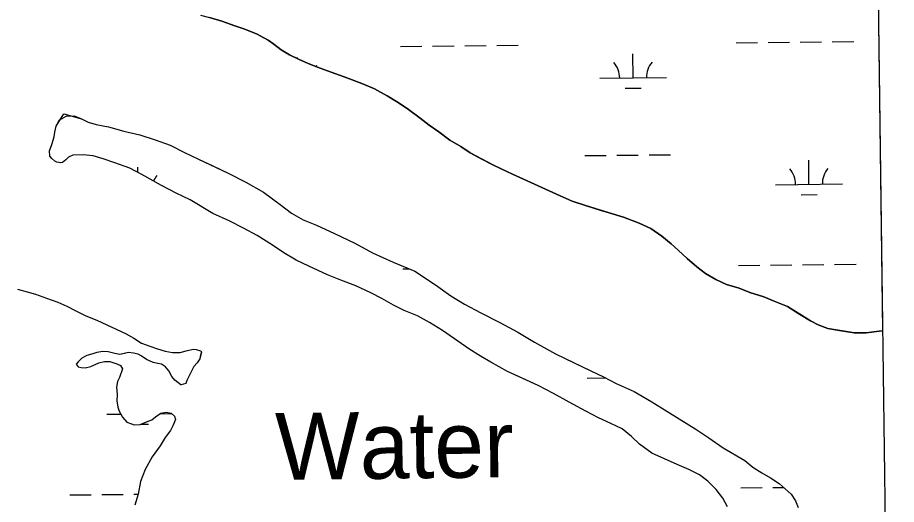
# Model space of a CAD drawing. Extents: x 3734862 to 3772949, y 391520 to 417239.
# Drawn here: x 3769529 to 3770844, y 398541 to 399269 of the extents above; entities that cross this region are included whole.
import ezdxf

# ---------------------------------------------------------------- set-up
doc = ezdxf.new("R2010")
doc.units = 0
for name, color, linetype in [('V-GRID-FRAM', 7, 'Continuous'), ('V-RIVR-IDEN', 7, 'Continuous'), ('V-TOPO-SHOR', 7, 'Continuous'), ('V-WETL-SWMP', 7, 'Continuous')]:
    doc.layers.add(name, color=color, linetype=linetype)

msp = doc.modelspace()

# ---------------------------------------------------------------- linework, layer by layer
at = {"layer": 'V-GRID-FRAM'}
msp.add_lwpolyline([(3738832.3, 415033.8), (3770599.2, 415447.4), (3770843.8, 397266.6), (3739061.1, 396852.8), (3738832.3, 415033.8)], dxfattribs=at)
at = {"layer": 'V-TOPO-SHOR'}
for points in [[(3769802.6, 399272.3), (3769816, 399268.8), (3769834.8, 399263.3), (3769854.3, 399256.6), (3769867.4, 399252), (3769886.5, 399244.5), (3769904.1, 399235.2), (3769912.5, 399229), (3769923.6, 399220.5), (3769935.9, 399213.1), (3769949.3, 399206.5), (3769963.8, 399200.3), (3769981.8, 399193.3), (3769998.3, 399187.4), (3770017.5, 399180.4), (3770029.7, 399175.7), (3770046.6, 399169), (3770063.1, 399162.4), (3770081.8, 399151.9), (3770096, 399143.4), (3770112, 399132.9), (3770131.2, 399118.6), (3770144.9, 399107.7), (3770159.1, 399098.1), (3770175.9, 399085.7), (3770192.4, 399076), (3770206.1, 399066.7), (3770223.7, 399057.3), (3770239.8, 399048.8), (3770252.4, 399042.6), (3770269.7, 399034.8), (3770340.9, 399002.1), (3770358.9, 398994.3), (3770378.5, 398987.6), (3770400.7, 398981), (3770414.1, 398977), (3770435.6, 398970.4), (3770459, 398961.4), (3770476.6, 398953.2), (3770493, 398942), (3770506.8, 398930.4), (3770517.1, 398921.1), (3770530.8, 398908.3), (3770545, 398896), (3770558, 398886.3), (3770573.7, 398877), (3770589.8, 398869.9), (3770608.5, 398864.1), (3770624.6, 398857.8), (3770645.3, 398851.2), (3770661, 398844.9), (3770680.6, 398836.7), (3770698.9, 398825.5), (3770715.4, 398815.4), (3770726.9, 398809.2), (3770741.4, 398803.7), (3770758.7, 398800.9), (3770780.6, 398797.3), (3770798.6, 398797.2), (3770817.8, 398799.8), (3770823.2, 398800.6)], [(3769577.4, 399061.8), (3769576.7, 399069.6), (3769580.2, 399079), (3769583.8, 399090.3), (3769584.6, 399097.3), (3769586.7, 399106.3), (3769598.5, 399124.8)], [(3769598.5, 399124.8), (3769624.6, 399117.3), (3769634.7, 399112.6), (3769646.4, 399109), (3769665.1, 399105.4), (3769688.1, 399099), (3769711.9, 399093.4), (3769734.9, 399086.2), (3769757.5, 399077.9), (3769778.9, 399067.2), (3769799.5, 399057.3), (3769821.3, 399047), (3769843.9, 399036.3), (3769870.4, 399022.9), (3769896.8, 399007.9), (3769922.1, 398989.4), (3769938.8, 398976.4), (3769956.3, 398966.5), (3769976.2, 398958.6), (3770003.4, 398945.9), (3770033.4, 398931.3), (3770059.9, 398917.1), (3770091, 398903.2), (3770123.3, 398889.4), (3770154.5, 398869.3), (3770177, 398852.7), (3770197.6, 398840.1), (3770222.1, 398827.1), (3770250.5, 398812.8), (3770277.4, 398798.6), (3770302.3, 398783.2), (3770333.8, 398765.9), (3770362.6, 398752), (3770386.8, 398740.6), (3770405.4, 398731.8), (3770424.5, 398721.6), (3770451.4, 398709.7), (3770477.8, 398694.3), (3770500.4, 398680.1), (3770522.6, 398666.3), (3770543.6, 398653.3), (3770563.4, 398640.3), (3770584.8, 398625.3), (3770617.1, 398606.4), (3770629.1, 398596.5), (3770642.3, 398588.3), (3770655.6, 398580.8), (3770668.4, 398572.1), (3770686.3, 398556), (3770692.8, 398546.2), (3770696.7, 398536)], [(3769642.2, 399062.2), (3769627.4, 399063.8), (3769611.8, 399063.2), (3769605.1, 399060.1), (3769601.2, 399056.2), (3769596.5, 399051.9), (3769593.7, 399051.6), (3769587.9, 399052.8), (3769584.8, 399054.3), (3769580.5, 399057.9), (3769577.4, 399061.8)], [(3770591.3, 398537.4), (3770584.3, 398550.4), (3770573.9, 398563.3), (3770561.8, 398575.5), (3770549, 398585.3), (3770533, 398592.8), (3770515.9, 398600.4), (3770496.8, 398609.1), (3770477.8, 398617.4), (3770459.5, 398630.8), (3770447.4, 398642.2), (3770433.5, 398653.6), (3770416.7, 398661.9), (3770398, 398670.2), (3770379.4, 398680.5), (3770354.1, 398693.5), (3770330.7, 398706.9), (3770307.8, 398718.8), (3770284, 398729.5), (3770262.2, 398739.4), (3770236.9, 398753.6), (3770221.7, 398762.7), (3770204.2, 398773.3), (3770182.8, 398788.3), (3770164.6, 398800.9), (3770145.1, 398812.7), (3770127.2, 398822.6), (3770107.4, 398830.9), (3770091.4, 398838.8), (3770073.9, 398848.7), (3770057.6, 398857.4), (3770035, 398867.7), (3770012.8, 398876), (3769992.5, 398884.3), (3769964.9, 398897), (3769945.8, 398906.1), (3769927.5, 398917.1), (3769910.4, 398928.6), (3769887.5, 398942.8), (3769867.2, 398953.8), (3769845.4, 398964.9), (3769821.3, 398976), (3769787.4, 398996.1), (3769766.4, 399006), (3769744.2, 399017.8), (3769715.1, 399034), (3769696.8, 399043.5), (3769674.6, 399051.8), (3769657, 399057.8), (3769642.2, 399062.2)], [(3769528.9, 398862.6), (3769543.3, 398858.6), (3769555.8, 398855), (3769572.2, 398849.4), (3769589.3, 398843.1), (3769603, 398837.5), (3769615, 398830.8), (3769631.4, 398822.9), (3769647.7, 398816.2), (3769691.3, 398796), (3769703, 398789.3), (3769714.7, 398781.8), (3769726.7, 398777.4), (3769738.4, 398773.4), (3769749.7, 398769.9), (3769760.7, 398767.8), (3769772.4, 398767.8), (3769781.4, 398770.4), (3769791.5, 398773.1), (3769796.2, 398772.7), (3769802.8, 398770.3), (3769804, 398769.1), (3769802.4, 398762.1), (3769801.6, 398758.6), (3769797.7, 398752.4), (3769792.9, 398746.9), (3769788.2, 398738), (3769782.3, 398725.9), (3769780.7, 398721.6), (3769774, 398719.7), (3769773.2, 398719.7), (3769764.3, 398726.4), (3769759.7, 398732.3), (3769755.4, 398740.5), (3769750.4, 398746.4), (3769744.5, 398750.4), (3769738.7, 398751.6), (3769731.7, 398753.2), (3769721.9, 398757.5), (3769714.2, 398763.1), (3769709.5, 398765.4), (3769702.5, 398767), (3769695.1, 398767.9), (3769689.2, 398766.7), (3769681.8, 398765.2), (3769674.4, 398766.4), (3769670.5, 398767.6), (3769664.6, 398769.2), (3769656.4, 398769.7), (3769647.8, 398767.8), (3769641.6, 398765.8), (3769632.6, 398763.6)], [(3769632.6, 398763.6), (3769625.1, 398759.3), (3769619.6, 398753.9), (3769616.9, 398750.4), (3769617.6, 398748.8), (3769618.4, 398748.4), (3769619.6, 398746.8), (3769624.3, 398745.6), (3769630.1, 398745.2), (3769638.7, 398747.1), (3769650.8, 398752.5), (3769659.1, 398754.4), (3769666.9, 398754.4), (3769677.8, 398750.8), (3769683.2, 398748.4), (3769685.9, 398743.7), (3769681.6, 398730.8), (3769678.4, 398724.6), (3769677.2, 398716.4), (3769677.9, 398705.1), (3769677.8, 398695.7), (3769679.3, 398686.4), (3769681.2, 398680.5), (3769685.9, 398671.5), (3769692.5, 398664), (3769703.4, 398660), (3769712.4, 398660.4), (3769722.1, 398664.2), (3769730, 398667.3), (3769735.5, 398671.9), (3769743.3, 398677.4), (3769751.5, 398678.9), (3769758.9, 398677.3), (3769763.6, 398672.6), (3769765.1, 398667.9)], [(3769765.1, 398667.9), (3769761.5, 398658.1), (3769757.6, 398651.5), (3769749.7, 398641), (3769742.2, 398628.2), (3769730.4, 398612.2), (3769719.7, 398592.8), (3769713, 398574.9), (3769709.4, 398556.1), (3769704.6, 398539.8)]]:
    msp.add_lwpolyline(points, dxfattribs=at)
at = {"layer": 'V-WETL-SWMP'}
for p, q in [((3770797.7, 400695.1), (3770823.2, 398800.6)), ((3769834.8, 399263.3), (3769816, 399268.8)), ((3769854.3, 399256.6), (3769834.8, 399263.3)), ((3769867.4, 399252), (3769854.3, 399256.6)), ((3769886.5, 399244.5), (3769867.4, 399252)), ((3769904.1, 399235.2), (3769886.5, 399244.5)), ((3769912.5, 399229), (3769904.1, 399235.2)), ((3769923.6, 399220.5), (3769912.5, 399229)), ((3770603.9, 399230.9), (3770635.9, 399231.3)), ((3770651.9, 399231.4), (3770683.9, 399231.8)), ((3770699.9, 399232), (3770731.9, 399232.3)), ((3770747.9, 399232.5), (3770779.9, 399232.8)), ((3769935.9, 399213.1), (3769923.6, 399220.5)), ((3770102.1, 399225.6), (3770134, 399226)), ((3770150, 399226.1), (3770182, 399226.5)), ((3770198, 399226.7), (3770230, 399227)), ((3770246, 399227.2), (3770278, 399227.5)), ((3769949.3, 399206.5), (3769935.9, 399213.1)), ((3769947.6, 399207.3), (3769947.6, 399209.3)), ((3769963.8, 399200.3), (3769949.3, 399206.5)), ((3770449.9, 399178.6), (3770449.5, 399214.6)), ((3769981.8, 399193.3), (3769963.8, 399200.3)), ((3769998.3, 399187.4), (3769981.8, 399193.3)), ((3770017.5, 399180.4), (3769998.3, 399187.4)), ((3770029.7, 399175.7), (3770017.5, 399180.4)), ((3770399.9, 399178), (3770499.9, 399179.1)), ((3770046.6, 399169), (3770029.7, 399175.7)), ((3770063.1, 399162.4), (3770046.6, 399169)), ((3770438, 399163), (3770462, 399163.3)), ((3770081.8, 399151.9), (3770063.1, 399162.4)), ((3770096, 399143.4), (3770081.8, 399151.9)), ((3770112, 399132.9), (3770096, 399143.4)), ((3770131.2, 399118.6), (3770112, 399132.9)), ((3770144.9, 399107.7), (3770131.2, 399118.6)), ((3770159.1, 399098.1), (3770144.9, 399107.7)), ((3770175.9, 399085.7), (3770159.1, 399098.1)), ((3770192.4, 399076), (3770175.9, 399085.7)), ((3770206.1, 399066.7), (3770192.4, 399076)), ((3770239.8, 399048.8), (3770206.1, 399066.7)), ((3770377.7, 399062.4), (3770409.7, 399062.7)), ((3770425.7, 399062.9), (3770457.7, 399063.2)), ((3770473.7, 399063.4), (3770505.7, 399063.7)), ((3769709, 399037.2), (3769708.9, 399044.9)), ((3770252.4, 399042.6), (3770239.8, 399048.8)), ((3770713, 399019.5), (3770712.6, 399055.5)), ((3770269.7, 399034.8), (3770252.4, 399042.6)), ((3770340.9, 399002.1), (3770269.7, 399034.8)), ((3770663, 399018.9), (3770763, 399020)), ((3770358.9, 398994.3), (3770340.9, 399002.1)), ((3770378.5, 398987.6), (3770358.9, 398994.3)), ((3770701.2, 399003.9), (3770725.2, 399004.2)), ((3770414.1, 398977), (3770378.5, 398987.6)), ((3770435.6, 398970.4), (3770414.1, 398977)), ((3770459, 398961.4), (3770435.6, 398970.4)), ((3770476.6, 398953.2), (3770459, 398961.4)), ((3770493, 398942), (3770476.6, 398953.2)), ((3770506.8, 398930.4), (3770493, 398942)), ((3770517.1, 398921.1), (3770506.8, 398930.4)), ((3770530.8, 398908.3), (3770517.1, 398921.1)), ((3770545, 398896), (3770530.8, 398908.3)), ((3770751.4, 398899.8), (3770783.4, 398900.1)), ((3770105.6, 398893), (3770114.7, 398893.1)), ((3770558, 398886.3), (3770545, 398896)), ((3770607.4, 398898.3), (3770639.4, 398898.6)), ((3770655.4, 398898.8), (3770687.4, 398899.1)), ((3770703.4, 398899.3), (3770735.4, 398899.6)), ((3770573.7, 398877), (3770558, 398886.3)), ((3770589.8, 398869.9), (3770573.7, 398877)), ((3770608.5, 398864.1), (3770589.8, 398869.9)), ((3770624.6, 398857.8), (3770608.5, 398864.1)), ((3770645.3, 398851.2), (3770624.6, 398857.8)), ((3770661, 398844.9), (3770645.3, 398851.2)), ((3770680.6, 398836.7), (3770661, 398844.9)), ((3770715.4, 398815.4), (3770680.6, 398836.7)), ((3770726.9, 398809.2), (3770715.4, 398815.4)), ((3770741.4, 398803.7), (3770726.9, 398809.2)), ((3770780.6, 398797.3), (3770741.4, 398803.7)), ((3770798.6, 398797.2), (3770780.6, 398797.3)), ((3770817.8, 398799.8), (3770798.6, 398797.2)), ((3770823.2, 398800.6), (3770817.8, 398799.8)), ((3770381.2, 398729.7), (3770408.9, 398730)), ((3769742.1, 398676.5), (3769759.5, 398676.7)), ((3769662.8, 398675.7), (3769683.6, 398675.9)), ((3769700.9, 398660.7), (3769701.7, 398660.7)), ((3769713.4, 398660.8), (3769724.9, 398660.9)), ((3770611, 398565.6), (3770643, 398566)), ((3770659, 398566.1), (3770674.8, 398566.3)), ((3769607.2, 398555), (3769639.2, 398555.4)), ((3769655.2, 398555.5), (3769687.2, 398555.9)), ((3769703.2, 398556), (3769709.4, 398556.1))]:
    msp.add_line(p, q, dxfattribs=at)
for points in [[(3770591.3, 398537.4), (3770584.3, 398550.4), (3770573.9, 398563.3), (3770561.8, 398575.5), (3770549, 398585.3), (3770533, 398592.8), (3770515.9, 398600.4), (3770496.8, 398609.1), (3770477.8, 398617.4), (3770459.5, 398630.8), (3770447.4, 398642.2), (3770433.5, 398653.6), (3770416.7, 398661.9), (3770398, 398670.2), (3770379.4, 398680.5), (3770354.1, 398693.5), (3770330.7, 398706.9), (3770307.8, 398718.8), (3770262.2, 398739.4), (3770236.9, 398753.6), (3770221.7, 398762.7), (3770204.2, 398773.3), (3770182.8, 398788.3), (3770164.6, 398800.9), (3770145.1, 398812.7), (3770127.2, 398822.6), (3770107.4, 398830.9), (3770091.4, 398838.8), (3770073.9, 398848.7), (3770057.6, 398857.4), (3770035, 398867.7), (3770012.8, 398876), (3769992.5, 398884.3), (3769964.9, 398897), (3769945.8, 398906.1), (3769927.5, 398917.1), (3769910.4, 398928.6), (3769887.5, 398942.8), (3769867.2, 398953.8), (3769845.4, 398964.9), (3769821.3, 398976), (3769787.4, 398996.1), (3769766.4, 399006), (3769744.2, 399017.8), (3769715.1, 399034), (3769696.8, 399043.5), (3769674.6, 399051.8), (3769657, 399057.8), (3769642.2, 399062.2), (3769627.4, 399063.8), (3769611.8, 399063.2), (3769605.1, 399060.1), (3769601.2, 399056.2), (3769596.5, 399051.9), (3769593.7, 399051.6), (3769587.9, 399052.8), (3769584.8, 399054.3), (3769580.5, 399057.9), (3769577.4, 399061.8), (3769576.7, 399069.6), (3769580.2, 399079), (3769583.8, 399090.3), (3769584.6, 399097.3), (3769586.7, 399106.3), (3769591.4, 399115.6), (3769601.6, 399121.4), (3769613.7, 399122.1), (3769624.6, 399117.3), (3769634.7, 399112.6), (3769646.4, 399109), (3769665.1, 399105.4), (3769688.1, 399099), (3769711.9, 399093.4), (3769734.9, 399086.2)], [(3769734.9, 399086.2), (3769757.5, 399077.9), (3769778.9, 399067.2), (3769799.5, 399057.3), (3769843.9, 399036.3), (3769870.4, 399022.9), (3769896.8, 399007.9), (3769922.1, 398989.4), (3769938.8, 398976.4), (3769956.3, 398966.5), (3769976.2, 398958.6), (3770003.4, 398945.9), (3770033.4, 398931.3), (3770059.9, 398917.1), (3770091, 398903.2), (3770123.3, 398889.4), (3770154.5, 398869.3), (3770177, 398852.7), (3770197.6, 398840.1), (3770222.1, 398827.1), (3770250.5, 398812.8), (3770277.4, 398798.6), (3770302.3, 398783.2), (3770333.8, 398765.9), (3770386.8, 398740.6), (3770405.4, 398731.8), (3770424.5, 398721.6), (3770451.4, 398709.7), (3770477.8, 398694.3), (3770500.4, 398680.1), (3770543.6, 398653.3), (3770563.4, 398640.3), (3770584.8, 398625.3), (3770617.1, 398606.4), (3770629.1, 398596.5), (3770642.3, 398588.3), (3770655.6, 398580.8), (3770668.4, 398572.1), (3770686.3, 398556), (3770692.8, 398546.2), (3770696.7, 398536)], [(3769528.9, 398862.6), (3769543.3, 398858.6), (3769555.8, 398855), (3769572.2, 398849.4), (3769589.3, 398843.1), (3769603, 398837.5), (3769615, 398830.8), (3769631.4, 398822.9), (3769647.7, 398816.2), (3769691.3, 398796), (3769703, 398789.3), (3769714.7, 398781.8), (3769726.7, 398777.4), (3769738.4, 398773.4), (3769749.7, 398769.9), (3769760.7, 398767.8), (3769772.4, 398767.8), (3769781.4, 398770.4), (3769791.5, 398773.1), (3769796.2, 398772.7), (3769802.8, 398770.3), (3769804, 398769.1), (3769801.6, 398758.6), (3769797.7, 398752.4), (3769792.9, 398746.9), (3769788.2, 398738), (3769782.3, 398725.9), (3769780.7, 398721.6), (3769774, 398719.7), (3769773.2, 398719.7), (3769764.3, 398726.4), (3769759.7, 398732.3), (3769755.4, 398740.5), (3769750.4, 398746.4), (3769744.5, 398750.4), (3769738.7, 398751.6), (3769731.7, 398753.2), (3769721.9, 398757.5), (3769714.2, 398763.1), (3769709.5, 398765.4), (3769702.5, 398767), (3769695.1, 398767.9), (3769681.8, 398765.2), (3769674.4, 398766.4), (3769670.5, 398767.6), (3769664.6, 398769.2), (3769656.4, 398769.7), (3769647.8, 398767.8), (3769641.6, 398765.8), (3769632.6, 398763.6), (3769625.1, 398759.3), (3769619.6, 398753.9), (3769616.9, 398750.4), (3769617.6, 398748.8), (3769618.4, 398748.4), (3769619.6, 398746.8), (3769624.3, 398745.6), (3769630.1, 398745.2), (3769638.7, 398747.1), (3769650.8, 398752.5), (3769659.1, 398754.4), (3769666.9, 398754.4), (3769677.8, 398750.8), (3769683.2, 398748.4), (3769685.9, 398743.7)], [(3769685.9, 398743.7), (3769681.6, 398730.8), (3769678.4, 398724.6), (3769677.2, 398716.4), (3769677.9, 398705.1), (3769677.8, 398695.7), (3769679.3, 398686.4), (3769681.2, 398680.5), (3769685.9, 398671.5), (3769692.5, 398664), (3769703.4, 398660), (3769712.4, 398660.4), (3769730, 398667.3), (3769735.5, 398671.9), (3769743.3, 398677.4), (3769751.5, 398678.9), (3769758.9, 398677.3), (3769763.6, 398672.6), (3769765.1, 398667.9), (3769761.5, 398658.1), (3769757.6, 398651.5), (3769749.7, 398641), (3769742.2, 398628.2), (3769730.4, 398612.2), (3769719.7, 398592.8), (3769713, 398574.9), (3769709.4, 398556.1), (3769704.6, 398539.8)]]:
    msp.add_lwpolyline(points, dxfattribs=at)
for centre, start, end in [((3770003.2, 399174.3), 139.8334, 142.455), ((3770394.6, 399178.5), 359.8334, 41.377), ((3770505.1, 399179.6), 139.8334, 181.377), ((3769764.5, 399009.9), 139.8334, 155.7378), ((3770657.8, 399019.4), 359.8334, 41.377), ((3770768.2, 399020.5), 139.8334, 181.377)]:
    msp.add_arc(centre, 35.2, start, end, dxfattribs=at)

# ---------------------------------------------------------------- texts
at = {"layer": 'V-RIVR-IDEN'}
msp.add_text('Water', height=100, rotation=0.7119, dxfattribs=at).set_placement((3769915.2, 398577.3))

doc.saveas('drawing.dxf')
